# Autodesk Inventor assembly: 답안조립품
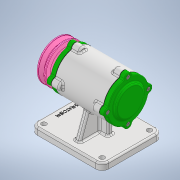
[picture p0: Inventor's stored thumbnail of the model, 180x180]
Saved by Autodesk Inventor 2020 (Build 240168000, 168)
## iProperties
Created: 2022-11
Part Number: 답안조립품
Document SubType Name: Assembly
Designer: owner
Author: owner
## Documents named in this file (12)
- C:\Users\owner\Desktop\721108V1007\답안조립품.iam
- C:\Users\owner\Desktop\721108V1007\본체.ipt
- C:\Users\owner\Desktop\721108V1007\V-벨트풀리.ipt
- C:\Users\owner\Desktop\721108V1007\개스킷.ipt
- C:\Users\owner\Desktop\721108V1007\너트 M12 x 1.25.ipt
- C:\Users\owner\Desktop\721108V1007\뒤커버.ipt
- C:\Users\owner\Desktop\721108V1007\베어링 6204.ipt
- C:\Users\owner\Desktop\721108V1007\볼트 M4 x 12.ipt
- C:\Users\owner\Desktop\721108V1007\앞커버.ipt
- C:\Users\owner\Desktop\721108V1007\오일 실.ipt
- C:\Users\owner\Desktop\721108V1007\축.ipt
- C:\Users\owner\Desktop\721108V1007\키 4 x 4.ipt
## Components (8 placed, 6 different names)
1. V-벨트풀리:1 — 플러쉬:2
2. 개스킷:1
3. KS B 1012 클래스 1 일반 - 미터 M12x1.25:1 — 플러쉬:2
4. KS B 2023 6204 - 20 x 47 x 14:1
5. KS B 2804 D D - 20 32 8:1 — 플러쉬:1
6. KS B 1311 (I) 4 x 4 x 12:1
7. KS B 2023 6204 - 20 x 47 x 14:2
8. 개스킷:2
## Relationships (2: Flush 2)
- 플러쉬:1 [Flush]: KS B 2804 D D - 20 32 8:1
- 플러쉬:2 [Flush]: V-벨트풀리:1 ↔ KS B 1012 클래스 1 일반 - 미터 M12x1.25:1
